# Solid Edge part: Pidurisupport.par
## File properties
Author: Türk
Template: iso part.par
Last saved by: Türk
Revision: 11
Application: Solid Edge
Accuracy: 0,990
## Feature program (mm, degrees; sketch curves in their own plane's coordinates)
thread "unnamed Thread 1"
thread "unnamed Thread 2"
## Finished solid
Body 1: solid body, 64 faces, 125 edges, 62 vertices.
  Faces by surface: plane 27, cylinder 22, cone 13, spline 2
  Edges by curve: circle 63, line 40, intersection 10, ellipse 8, curve on surface 4
Bounding box of the edges (mm; curved faces can reach further): 96.748 x 152.000 x 85.456, from (-27.7472, -82, -26.5) to (69.0008, 70, 58.9555).
Cylindrical faces by radius (mm): R4 x8, R5 x2, R10 x6, R12.5 x3, R60 x2, R100 x1
Conical faces (half-angle, radius in mm at the cone's reference point): 45 deg R5 x2, 45 deg R12.5 x6, 45 deg R60 x1, 45 deg R61 x2, 45 deg R99 x1, 45 deg R100 x1
Planar faces by outward normal: +x 2, +y 7, -y 8, -z 2, oblique 8
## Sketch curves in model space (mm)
line (0, 0, 0) -> (42.5, 0, 35)
arc centre (69.0008, 0, -40.4832) radius 60 from (60.4294, 0, 18.9014) through (31.1697, 0, 6.0873) to (12.6323, 0, -19.9262)
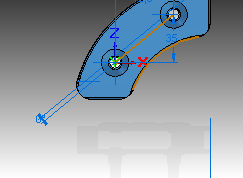
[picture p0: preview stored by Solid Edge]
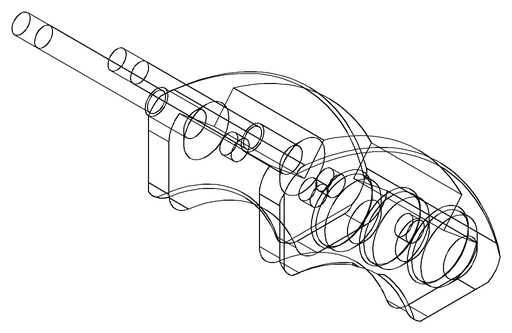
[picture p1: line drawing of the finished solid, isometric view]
